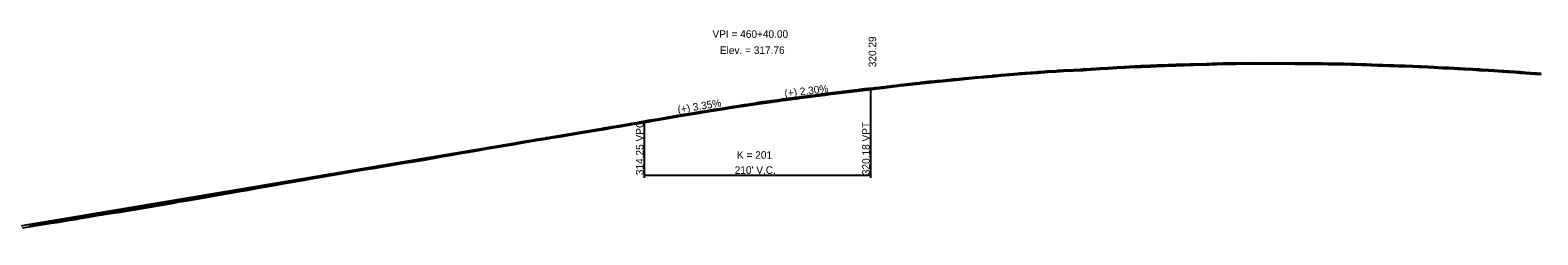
# Model space of a CAD drawing. Extents: x 1876258 to 1926563, y 729739 to 834437.
# Drawn here: x 1923728 to 1925127, y 831470 to 831660 of the extents above; entities that cross this region are included whole.
import ezdxf

# ---------------------------------------------------------------- set-up
doc = ezdxf.new("R2010")
doc.units = 0
for name, color, linetype in [('RD_EX_BldgApp', 7, 'Continuous'), ('RD_EX_H2O_BlueLn', 7, 'Continuous'), ('RD_EX_RailRoad', 7, 'Continuous'), ('RD_HC_Data', 7, 'Continuous'), ('RD_HC_Data_Tic', 7, 'Continuous'), ('RD_HC_TX_Sta50', 7, 'Continuous'), ('RD_PD_ALT5_CL', 7, 'Continuous')]:
    doc.layers.add(name, color=color, linetype=linetype)

msp = doc.modelspace()

# ---------------------------------------------------------------- linework, layer by layer
at = {"layer": 'RD_EX_BldgApp'}
for points in [[(1924744.1, 831625.2), (1924752.5, 831625.7), (1924759.1, 831626), (1924767.4, 831626.3), (1924773.7, 831626.6), (1924780.8, 831626.9), (1924791.2, 831627.2), (1924799.4, 831627.4), (1924807.7, 831627.7), (1924814.5, 831627.9), (1924822.2, 831628.1), (1924829.3, 831628.4), (1924839.1, 831628.6), (1924846.7, 831628.7), (1924854.1, 831628.8), (1924862.6, 831628.8), (1924870.1, 831628.8), (1924878.5, 831628.8), (1924886, 831628.8), (1924894.5, 831628.8), (1924901.9, 831628.7), (1924910.4, 831628.7), (1924917.4, 831628.6), (1924926.4, 831628.5), (1924933, 831628.4), (1924940.2, 831628.3), (1924946.5, 831628.2), (1924954.1, 831628), (1924960.8, 831627.9), (1924963.7, 831627.7), (1924966.2, 831627.7), (1924972.5, 831627.4), (1924978.8, 831627.1), (1924983.3, 831627.1), (1924988.9, 831626.9), (1924997.5, 831626.6), (1925003, 831626.4), (1925011.4, 831626.1), (1925016.9, 831625.8), (1925025.2, 831625.5), (1925030.8, 831625.2), (1925039.1, 831624.7), (1925044.7, 831624.5), (1925053.1, 831624.1), (1925058.6, 831623.8), (1925067, 831623.3), (1925073.1, 831622.9), (1925081.6, 831622.5), (1925086.3, 831622.2), (1925094.8, 831621.6), (1925099.1, 831621.3), (1925105.4, 831620.8), (1925111.1, 831620.4), (1925116, 831620), (1925124.7, 831619.4), (1925130.3, 831618.9)], [(1923930.2, 831511.8), (1923939, 831513.5), (1923946.6, 831514.8), (1923955.4, 831516.4), (1923963.5, 831517.7), (1923971.3, 831519), (1923976.5, 831520), (1923982.2, 831521), (1923992.1, 831522.8), (1923997.9, 831523.7), (1924006.7, 831525.3), (1924014.1, 831526.6), (1924023, 831528), (1924030.1, 831529.2), (1924038.9, 831530.7), (1924046.2, 831531.9), (1924054.9, 831533.3), (1924062.4, 831534.6), (1924071, 831536.1), (1924078.5, 831537.3), (1924087.2, 831538.7), (1924094.6, 831539.9), (1924103.2, 831541.5), (1924110.8, 831542.8), (1924119.3, 831544.3), (1924126.8, 831545.6), (1924135, 831546.9), (1924142.5, 831548.3), (1924150.1, 831549.6), (1924161.8, 831551.5), (1924167.2, 831552.4), (1924177, 831554.1), (1924181.6, 831554.9), (1924190.4, 831556.4), (1924197.4, 831557.7), (1924206.2, 831559.1), (1924213, 831560.2), (1924221.8, 831561.6), (1924228.4, 831562.7), (1924237.4, 831564.2), (1924244.9, 831565.4), (1924254, 831567), (1924260.8, 831568.1), (1924269.9, 831569.7), (1924276.6, 831570.9), (1924286.2, 831572.6), (1924292.8, 831573.7), (1924301.7, 831575.2), (1924308.4, 831576.4), (1924317.5, 831578), (1924324.2, 831579.1), (1924333.3, 831580.6), (1924339.3, 831581.6), (1924346.8, 831582.8), (1924354.4, 831584), (1924359.8, 831584.9), (1924366.5, 831586), (1924375.7, 831587.5), (1924383.4, 831588.6), (1924392.5, 831590.1), (1924400.3, 831591.1), (1924409.2, 831592.5), (1924416.2, 831593.5), (1924425.1, 831594.9), (1924434.2, 831596.1), (1924441.6, 831597), (1924450.8, 831598.2), (1924456.9, 831599), (1924462.9, 831599.9), (1924472.1, 831601.1), (1924481.5, 831602.2), (1924494.5, 831603.7), (1924502.5, 831604.7), (1924506, 831605.1), (1924512.7, 831605.7), (1924519.2, 831606.5), (1924528.4, 831607.5), (1924535.7, 831608.4), (1924544.7, 831609.6), (1924553.4, 831610.5), (1924562.1, 831611.4), (1924590.3, 831614.1), (1924598.8, 831614.9), (1924607.4, 831615.8), (1924612.9, 831616.2), (1924621.4, 831617), (1924628.7, 831617.7), (1924637.2, 831618.4), (1924644.7, 831619.1), (1924652.6, 831619.7), (1924663.1, 831620.4), (1924672.6, 831621.1), (1924680.2, 831621.6), (1924691.3, 831622.3), (1924696.7, 831622.5), (1924705.2, 831622.9), (1924712.5, 831623.4), (1924720.9, 831623.9), (1924728.2, 831624.3), (1924736.8, 831624.8), (1924744.1, 831625.2)], [(1923720.5, 831476.7), (1923730.3, 831478.3), (1923737.6, 831479.5), (1923747.4, 831481), (1923754.6, 831482.1), (1923764.5, 831483.7), (1923771.6, 831484.8), (1923771.6, 831484.9), (1923782, 831486.6), (1923788.4, 831487.7), (1923796.2, 831489), (1923804.3, 831490.3), (1923811.6, 831491.3), (1923816.7, 831492.2), (1923826.1, 831493.8), (1923833.2, 831495), (1923842.5, 831496.6), (1923849.7, 831497.8), (1923858.9, 831499.4), (1923866.2, 831500.7), (1923875.2, 831502.2), (1923881.9, 831503.3), (1923890.7, 831504.9), (1923897.4, 831506.1), (1923906.3, 831507.7), (1923913.3, 831508.9), (1923922.2, 831510.4), (1923930.2, 831511.8)]]:
    msp.add_lwpolyline(points, dxfattribs=at)
at = {"layer": 'RD_EX_H2O_BlueLn'}
for p, q in [((1924508.1, 831523.1), (1924508.1, 831605.2)), ((1924298.1, 831523.1), (1924298.1, 831575.6)), ((1924298.1, 831525.6), (1924508.1, 831525.6))]:
    msp.add_line(p, q, dxfattribs=at)
at = {"layer": 'RD_HC_Data_Tic'}
msp.add_lwpolyline([(1923726.8, 831479), (1923730.1, 831479.5), (1923731.9, 831479.8), (1923737, 831480.6), (1923737.4, 831480.7), (1923742.1, 831481.4), (1923747.2, 831482.2), (1923747.2, 831482.2), (1923752.4, 831483), (1923754.4, 831483.3), (1923757.4, 831483.8), (1923762.6, 831484.6), (1923764.3, 831484.9), (1923767.7, 831485.5), (1923771.4, 831486.1), (1923771.5, 831486.1), (1923772.8, 831486.3), (1923777.9, 831487.2), (1923781.8, 831487.8), (1923783, 831488), (1923788.1, 831488.9), (1923788.2, 831488.9), (1923793.2, 831489.7), (1923796, 831490.2), (1923798.3, 831490.6), (1923803.4, 831491.4), (1923804.1, 831491.5), (1923808.5, 831492.2), (1923811.4, 831492.6), (1923813.6, 831493), (1923816.5, 831493.4), (1923818.7, 831493.8), (1923823.8, 831494.7), (1923825.9, 831495), (1923828.9, 831495.5), (1923833, 831496.2), (1923834, 831496.4), (1923839.1, 831497.3), (1923842.3, 831497.8), (1923844.3, 831498.2), (1923849.4, 831499), (1923849.5, 831499.1), (1923854.5, 831499.9), (1923858.7, 831500.6), (1923859.6, 831500.8), (1923864.7, 831501.7), (1923866, 831501.9), (1923869.8, 831502.6), (1923874.9, 831503.4), (1923875, 831503.4), (1923880, 831504.3), (1923881.7, 831504.6), (1923885.1, 831505.2), (1923890.2, 831506.1), (1923890.5, 831506.2), (1923895.3, 831507), (1923897.2, 831507.4), (1923900.4, 831507.9), (1923905.5, 831508.8), (1923906.1, 831508.9), (1923910.6, 831509.7), (1923913.1, 831510.1), (1923915.7, 831510.6), (1923920.8, 831511.5), (1923921.9, 831511.6), (1923926, 831512.3), (1923929.9, 831513), (1923931, 831513.2), (1923936.1, 831514.2), (1923938.8, 831514.7), (1923941.3, 831515.2), (1923946.3, 831516.1), (1923946.4, 831516.1), (1923951.5, 831517), (1923955.1, 831517.6), (1923956.6, 831517.9), (1923961.7, 831518.7), (1923963.3, 831519), (1923966.8, 831519.6), (1923971.1, 831520.3), (1923971.9, 831520.4), (1923976.3, 831521.2), (1923977, 831521.3), (1923982, 831522.3), (1923982.1, 831522.3), (1923987.2, 831523.2), (1923991.9, 831524), (1923992.4, 831524.1), (1923997.5, 831524.9), (1923997.7, 831524.9), (1924002.5, 831525.8), (1924006.5, 831526.5), (1924007.7, 831526.7), (1924012.8, 831527.6), (1924013.9, 831527.8), (1924017.9, 831528.5), (1924022.7, 831529.3), (1924023, 831529.3), (1924028.1, 831530.2), (1924029.9, 831530.5), (1924033.2, 831531), (1924038.3, 831531.8), (1924038.7, 831531.9), (1924043.4, 831532.7), (1924046, 831533.1), (1924048.5, 831533.5), (1924053.6, 831534.4), (1924054.7, 831534.5), (1924058.7, 831535.2), (1924062.2, 831535.8), (1924063.8, 831536.1), (1924068.9, 831537), (1924070.8, 831537.3), (1924074.1, 831537.8), (1924078.3, 831538.5), (1924079.2, 831538.7), (1924084.3, 831539.5), (1924087, 831539.9), (1924089.4, 831540.3), (1924094.4, 831541.2), (1924094.5, 831541.2), (1924099.6, 831542.1), (1924103, 831542.7), (1924104.7, 831543), (1924109.8, 831543.9), (1924110.6, 831544), (1924114.9, 831544.8), (1924119.1, 831545.6), (1924120, 831545.7), (1924125.1, 831546.6), (1924126.6, 831546.8), (1924130.2, 831547.4), (1924134.7, 831548.2), (1924135.3, 831548.3), (1924140.4, 831549.2), (1924142.3, 831549.5), (1924145.5, 831550.1), (1924149.9, 831550.8), (1924150.6, 831550.9), (1924155.8, 831551.8), (1924160.9, 831552.6), (1924161.6, 831552.8), (1924166, 831553.5), (1924167, 831553.6), (1924171.1, 831554.3), (1924176.2, 831555.3), (1924176.7, 831555.4), (1924181.3, 831556.1), (1924181.4, 831556.1), (1924186.4, 831557), (1924190.2, 831557.7), (1924191.5, 831557.9), (1924196.6, 831558.8), (1924197.2, 831558.9), (1924201.7, 831559.6), (1924206, 831560.3), (1924206.8, 831560.4), (1924211.9, 831561.3), (1924212.8, 831561.4), (1924217, 831562.1), (1924221.6, 831562.8), (1924222.1, 831562.9), (1924227.2, 831563.8), (1924228.2, 831563.9), (1924232.4, 831564.6), (1924237.2, 831565.4), (1924237.5, 831565.4), (1924242.6, 831566.3), (1924244.7, 831566.6), (1924247.7, 831567.1), (1924252.8, 831568), (1924253.8, 831568.2), (1924257.9, 831568.9), (1924260.6, 831569.4), (1924263, 831569.8), (1924268.1, 831570.7), (1924269.7, 831570.9), (1924273.2, 831571.5), (1924276.4, 831572.1), (1924278.3, 831572.4), (1924283.4, 831573.3), (1924286, 831573.8), (1924288.5, 831574.2), (1924292.5, 831574.9), (1924293.6, 831575.1), (1924298.7, 831576), (1924301.5, 831576.5), (1924303.9, 831576.9), (1924308.2, 831577.6), (1924308.9, 831577.7), (1924314, 831578.6), (1924317.3, 831579.2), (1924319.2, 831579.5), (1924324, 831580.3), (1924324.3, 831580.4), (1924329.4, 831581.2), (1924333.1, 831581.9), (1924334.5, 831582.1), (1924339.1, 831582.8), (1924339.6, 831582.9), (1924344.7, 831583.7), (1924346.6, 831584), (1924349.8, 831584.6), (1924354.1, 831585.2), (1924354.9, 831585.4), (1924359.6, 831586.2), (1924360, 831586.2), (1924365.1, 831587.1), (1924366.3, 831587.2), (1924370.2, 831587.9), (1924375.4, 831588.7), (1924375.5, 831588.7), (1924380.5, 831589.5), (1924383.2, 831589.9), (1924385.6, 831590.3), (1924390.7, 831591.1), (1924392.3, 831591.3), (1924395.8, 831591.8), (1924400.1, 831592.4), (1924400.9, 831592.5), (1924406, 831593.3), (1924409, 831593.7), (1924411.1, 831594), (1924416, 831594.7), (1924416.2, 831594.8), (1924421.3, 831595.5), (1924424.9, 831596.1), (1924426.4, 831596.3), (1924431.6, 831597), (1924434, 831597.3), (1924436.7, 831597.7), (1924441.5, 831598.3), (1924441.8, 831598.3), (1924446.9, 831599), (1924450.7, 831599.5), (1924452, 831599.6), (1924456.8, 831600.3), (1924457.1, 831600.3), (1924462.2, 831601), (1924462.7, 831601.1), (1924467.3, 831601.7), (1924472, 831602.3), (1924472.4, 831602.4), (1924477.5, 831603), (1924481.3, 831603.4), (1924482.6, 831603.6), (1924487.7, 831604.2), (1924492.9, 831604.7), (1924494.4, 831604.9), (1924498, 831605.4), (1924502.3, 831605.9), (1924503.1, 831606), (1924505.9, 831606.3), (1924508.2, 831606.5), (1924512.5, 831607), (1924513.3, 831607), (1924518.4, 831607.7), (1924519.1, 831607.7), (1924523.5, 831608.3), (1924528.3, 831608.8), (1924528.6, 831608.8), (1924533.7, 831609.4), (1924535.6, 831609.7), (1924538.8, 831610.1), (1924543.9, 831610.7), (1924544.6, 831610.8), (1924549, 831611.3), (1924553.3, 831611.7), (1924554.1, 831611.8), (1924559.2, 831612.4), (1924561.9, 831612.7), (1924564.4, 831612.9), (1924569.5, 831613.4), (1924574.6, 831613.9), (1924579.7, 831614.4), (1924584.8, 831614.9), (1924589.9, 831615.3), (1924590.2, 831615.4), (1924595, 831615.8), (1924598.7, 831616.2), (1924600.1, 831616.3), (1924605.2, 831616.8), (1924607.3, 831617), (1924610.3, 831617.3), (1924612.8, 831617.5), (1924615.4, 831617.7), (1924620.5, 831618.2), (1924621.3, 831618.3), (1924625.7, 831618.7), (1924628.6, 831618.9), (1924630.8, 831619.1), (1924635.9, 831619.6), (1924637.1, 831619.7), (1924641, 831620), (1924644.6, 831620.3), (1924646.1, 831620.5), (1924651.2, 831620.9), (1924652.5, 831621), (1924656.3, 831621.2), (1924661.4, 831621.6), (1924663.1, 831621.7), (1924666.5, 831621.9), (1924671.6, 831622.3), (1924672.5, 831622.4), (1924676.8, 831622.6), (1924680.1, 831622.9), (1924681.9, 831623), (1924687, 831623.3), (1924691.2, 831623.5), (1924692.1, 831623.5), (1924696.6, 831623.7), (1924697.2, 831623.7), (1924702.3, 831624), (1924705.1, 831624.2), (1924707.4, 831624.3), (1924712.4, 831624.7), (1924712.5, 831624.7), (1924717.6, 831624.9), (1924720.9, 831625.1), (1924722.7, 831625.2), (1924727.8, 831625.5), (1924728.2, 831625.5), (1924732.9, 831625.8), (1924736.7, 831626.1), (1924738.1, 831626.1), (1924743.2, 831626.4), (1924744, 831626.4), (1924748.3, 831626.7), (1924752.4, 831626.9), (1924753.4, 831627), (1924758.5, 831627.3), (1924759, 831627.3), (1924763.6, 831627.5), (1924767.3, 831627.6), (1924768.7, 831627.6), (1924773.6, 831627.9), (1924773.8, 831627.9), (1924778.9, 831628.1), (1924780.8, 831628.1), (1924784, 831628.2), (1924789.1, 831628.4), (1924791.2, 831628.5), (1924794.3, 831628.5), (1924799.3, 831628.7), (1924799.3, 831628.7), (1924804.5, 831628.8), (1924807.7, 831629), (1924809.6, 831629), (1924814.5, 831629.1), (1924814.7, 831629.1), (1924819.8, 831629.3), (1924822.1, 831629.4), (1924824.9, 831629.5), (1924829.3, 831629.6), (1924830, 831629.7), (1924835.1, 831629.8), (1924839.1, 831629.9), (1924840.2, 831629.9), (1924845.3, 831629.9), (1924846.7, 831629.9), (1924850.4, 831630), (1924854.1, 831630), (1924855.6, 831630), (1924860.7, 831630), (1924862.6, 831630.1), (1924865.8, 831630), (1924870.1, 831630), (1924870.9, 831630), (1924876, 831630), (1924878.5, 831630), (1924881.1, 831630), (1924886, 831630.1), (1924886.2, 831630.1), (1924891.3, 831630), (1924894.5, 831630), (1924896.4, 831630), (1924901.5, 831629.9), (1924901.9, 831629.9), (1924906.6, 831629.9), (1924910.4, 831629.9), (1924911.7, 831629.9), (1924916.9, 831629.9), (1924917.4, 831629.9), (1924922, 831629.8), (1924926.4, 831629.8), (1924927.1, 831629.8), (1924932.2, 831629.7), (1924933.1, 831629.6), (1924937.3, 831629.6), (1924940.2, 831629.5), (1924942.4, 831629.5), (1924946.6, 831629.5), (1924947.5, 831629.5), (1924952.6, 831629.3), (1924954.1, 831629.3), (1924957.7, 831629.2), (1924960.8, 831629.1), (1924962.9, 831629), (1924963.8, 831629), (1924966.3, 831628.9), (1924968, 831628.8), (1924972.6, 831628.6), (1924973.1, 831628.6), (1924978.2, 831628.3), (1924978.8, 831628.3), (1924983.2, 831628.4), (1924983.3, 831628.4), (1924988.4, 831628.1), (1924988.9, 831628.1), (1924993.5, 831628), (1924997.5, 831627.8), (1924998.6, 831627.8), (1925003.1, 831627.6), (1925003.7, 831627.6), (1925008.8, 831627.4), (1925011.4, 831627.4), (1925013.9, 831627.2), (1925017, 831627.1), (1925019, 831627), (1925024.1, 831626.8), (1925025.3, 831626.7), (1925029.3, 831626.5), (1925030.9, 831626.4), (1925034.4, 831626.2), (1925039.2, 831626), (1925039.5, 831626), (1925044.6, 831625.7), (1925044.7, 831625.7), (1925049.7, 831625.5), (1925053.1, 831625.3), (1925054.8, 831625.2), (1925058.6, 831625), (1925059.9, 831624.9), (1925065, 831624.7), (1925067, 831624.6), (1925070.1, 831624.4), (1925073.2, 831624.2), (1925075.2, 831624.1), (1925080.3, 831623.8), (1925081.6, 831623.8), (1925085.4, 831623.5), (1925086.4, 831623.4), (1925090.6, 831623.1), (1925094.9, 831622.8), (1925095.7, 831622.8), (1925099.2, 831622.5), (1925100.8, 831622.4), (1925105.5, 831622.1), (1925105.9, 831622.1), (1925111, 831621.7), (1925111.2, 831621.7), (1925116.1, 831621.3), (1925116.1, 831621.3), (1925121.2, 831620.9), (1925124.8, 831620.6), (1925126.3, 831620.5), (1925130.4, 831620.2)], dxfattribs=at)
at = {"layer": 'RD_HC_TX_Sta50'}
for p in [(1924482.6, 831602.3), (1924324.2, 831579.9)]:
    msp.add_line(p, (1924403.1, 831593.1), dxfattribs=at)
at = {"layer": 'RD_PD_ALT5_CL'}
for p, q in [((1924508.1, 831605.2), (1924513.1, 831605.8)), ((1923668.1, 831470.2), (1924298.1, 831575.6))]:
    msp.add_line(p, q, dxfattribs=at)
msp.add_spline([(1924298.1, 831575.6), (1924302.3, 831576.3), (1924306.5, 831576.9), (1924310.7, 831577.6), (1924314.9, 831578.3), (1924319.1, 831579), (1924323.3, 831579.7), (1924327.5, 831580.4), (1924331.7, 831581), (1924335.9, 831581.7), (1924340.1, 831582.4), (1924344.3, 831583), (1924348.5, 831583.7), (1924352.7, 831584.3), (1924356.9, 831585), (1924361.1, 831585.6), (1924365.3, 831586.2), (1924369.5, 831586.9), (1924373.7, 831587.5), (1924377.9, 831588.1), (1924382.1, 831588.7), (1924386.3, 831589.3), (1924390.5, 831589.9), (1924394.7, 831590.5), (1924398.9, 831591.1), (1924403.1, 831591.7), (1924407.3, 831592.3), (1924411.5, 831592.9), (1924415.7, 831593.5), (1924419.9, 831594.1), (1924424.1, 831594.7), (1924428.3, 831595.2), (1924432.5, 831595.8), (1924436.7, 831596.3), (1924440.9, 831596.9), (1924445.1, 831597.5), (1924449.3, 831598), (1924453.5, 831598.5), (1924457.7, 831599.1), (1924461.9, 831599.6), (1924466.1, 831600.1), (1924470.3, 831600.7), (1924474.5, 831601.2), (1924478.7, 831601.7), (1924482.9, 831602.2), (1924487.1, 831602.7), (1924491.3, 831603.2), (1924495.5, 831603.7), (1924499.7, 831604.2), (1924503.9, 831604.7), (1924508.1, 831605.2)], degree=3, dxfattribs=at)

# ---------------------------------------------------------------- texts
at = {"layer": 'RD_EX_H2O_BlueLn'}
for s, p in [('K = 201', (1924383.9, 831540.8)), ("210' V.C.", (1924381.8, 831526.8))]:
    msp.add_text(s, height=7, dxfattribs=at).set_placement(p)
at = {"layer": 'RD_EX_RailRoad'}
for s, p in [('314.25 VPC', (1924297.1, 831525.6)), ('320.18 VPT', (1924507.1, 831525.6))]:
    msp.add_text(s, height=7, rotation=90, dxfattribs=at).set_placement(p)
at = {"layer": 'RD_HC_Data'}
for s, p in [('VPI = 460+40.00', (1924361.1, 831653.1)), ('Elev. = 317.76', (1924368, 831638.1))]:
    msp.add_text(s, height=7, dxfattribs=at).set_placement(p)
msp.add_text('320.29', height=7, rotation=90, dxfattribs=at).set_placement((1924513.1, 831625.8))
at = {"layer": 'RD_HC_TX_Sta50'}
for s, rotation, p in [('(+) 2.30%', 6.5602, (1924428.4, 831598)), ('(+) 3.35%', 9.4961, (1924329.4, 831582.8))]:
    msp.add_text(s, height=7, rotation=rotation, dxfattribs=at).set_placement(p)

doc.saveas('drawing.dxf')
